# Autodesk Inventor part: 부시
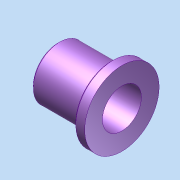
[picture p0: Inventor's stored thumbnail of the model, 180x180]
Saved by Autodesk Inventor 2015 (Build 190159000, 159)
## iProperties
Created: 2026-09
Part Number: 부시
Material: 일반
Document SubType Name: Modeling
Designer: SCD-A06
Density: 1 g/cm^3
Appearance: 기본값
Author: SCD-A06
Author: jhkim
Creation Date: 2026-08-27
Sending System: Autodesk Inventor 2027
Preprocessor: ST-DEVELOPER v20.1
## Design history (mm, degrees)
node "부시1"
node "솔리드1"
node "기준1"
